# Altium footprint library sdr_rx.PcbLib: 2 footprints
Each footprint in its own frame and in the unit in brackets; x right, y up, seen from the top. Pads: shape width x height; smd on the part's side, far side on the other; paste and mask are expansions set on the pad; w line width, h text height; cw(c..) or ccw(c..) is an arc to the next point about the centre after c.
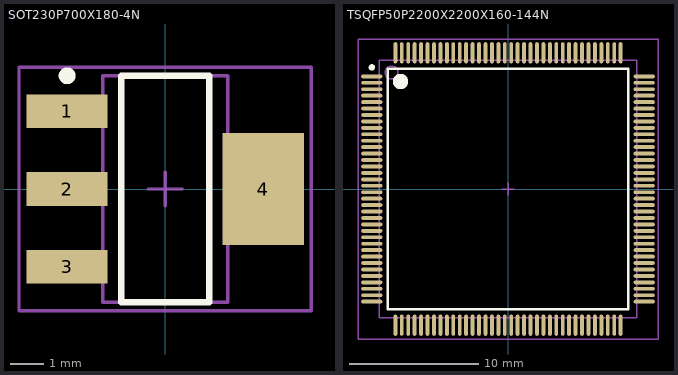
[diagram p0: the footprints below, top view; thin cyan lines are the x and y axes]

## SOT230P700X180-4N [mm] "SOT223, 4-Leads, Body 6.7x7.3mm (max), Pitch 2.30mm, IPC Medium Density"
height 1.8
pads (4):
  rect 2.4x1 smd: 1(-2.9,2.3) 2(-2.9,0) 3(-2.9,-2.3)
  rect 2.4x3.3 smd: 4(2.9,0)
Top Overlay:
  circle w0.25: c-2.9,3.35 r0.125
  lines w0.2: -1.3,-3.35 -1.3,3.35 1.3,3.35 1.3,-3.35 -1.3,-3.35
Mechanical 13:
  lines w0.1: -1.85,-3.35 -1.85,3.35 1.85,3.35 1.85,-3.35 -1.85,-3.35
Mechanical 15:
  lines w0.1: -0.5,0 0.5,0 ; 0,-0.5 0,0.5 ; -4.325,-3.6 -4.325,3.6 4.325,3.6 4.325,-3.6 -4.325,-3.6
3D body: height 1.8, standoff 0.02, extent -1.85,-3.35 1.85,3.35

## TSQFP50P2200X2200X160-144N [mm] "TSQFP, 144-Leads, Body 22.0x22.0mm (max), Pitch 0.50mm, IPC Medium Density"
height 1.6
pads (144):
  oval 1.65x0.3 smd: 1(-10.575,8.75) 2(-10.575,8.25) 3(-10.575,7.75) 4(-10.575,7.25) 5(-10.575,6.75) 6(-10.575,6.25) 7(-10.575,5.75) 8(-10.575,5.25) 9(-10.575,4.75) 10(-10.575,4.25) 11(-10.575,3.75) 12(-10.575,3.25) 13(-10.575,2.75) 14(-10.575,2.25) 15(-10.575,1.75) 16(-10.575,1.25) 17(-10.575,0.75) 18(-10.575,0.25) 19(-10.575,-0.25) 20(-10.575,-0.75) 21(-10.575,-1.25) 22(-10.575,-1.75) 23(-10.575,-2.25) 24(-10.575,-2.75) 25(-10.575,-3.25) 26(-10.575,-3.75) 27(-10.575,-4.25) 28(-10.575,-4.75) 29(-10.575,-5.25) 30(-10.575,-5.75) 31(-10.575,-6.25) 32(-10.575,-6.75) 33(-10.575,-7.25) 34(-10.575,-7.75) 35(-10.575,-8.25) 36(-10.575,-8.75) 73(10.575,-8.75) 74(10.575,-8.25) 75(10.575,-7.75) 76(10.575,-7.25) 77(10.575,-6.75) 78(10.575,-6.25) 79(10.575,-5.75) 80(10.575,-5.25) 81(10.575,-4.75) 82(10.575,-4.25) 83(10.575,-3.75) 84(10.575,-3.25) 85(10.575,-2.75) 86(10.575,-2.25) 87(10.575,-1.75) 88(10.575,-1.25) 89(10.575,-0.75) 90(10.575,-0.25) 91(10.575,0.25) 92(10.575,0.75) 93(10.575,1.25) 94(10.575,1.75) 95(10.575,2.25) 96(10.575,2.75) 97(10.575,3.25) 98(10.575,3.75) 99(10.575,4.25) 100(10.575,4.75) 101(10.575,5.25) 102(10.575,5.75) 103(10.575,6.25) 104(10.575,6.75) 105(10.575,7.25) 106(10.575,7.75) 107(10.575,8.25) 108(10.575,8.75)
  oval 0.3x1.65 smd: 37(-8.75,-10.575) 38(-8.25,-10.575) 39(-7.75,-10.575) 40(-7.25,-10.575) 41(-6.75,-10.575) 42(-6.25,-10.575) 43(-5.75,-10.575) 44(-5.25,-10.575) 45(-4.75,-10.575) 46(-4.25,-10.575) 47(-3.75,-10.575) 48(-3.25,-10.575) 49(-2.75,-10.575) 50(-2.25,-10.575) 51(-1.75,-10.575) 52(-1.25,-10.575) 53(-0.75,-10.575) 54(-0.25,-10.575) 55(0.25,-10.575) 56(0.75,-10.575) 57(1.25,-10.575) 58(1.75,-10.575) 59(2.25,-10.575) 60(2.75,-10.575) 61(3.25,-10.575) 62(3.75,-10.575) 63(4.25,-10.575) 64(4.75,-10.575) 65(5.25,-10.575) 66(5.75,-10.575) 67(6.25,-10.575) 68(6.75,-10.575) 69(7.25,-10.575) 70(7.75,-10.575) 71(8.25,-10.575) 72(8.75,-10.575) 109(8.75,10.575) 110(8.25,10.575) 111(7.75,10.575) 112(7.25,10.575) 113(6.75,10.575) 114(6.25,10.575) 115(5.75,10.575) 116(5.25,10.575) 117(4.75,10.575) 118(4.25,10.575) 119(3.75,10.575) 120(3.25,10.575) 121(2.75,10.575) 122(2.25,10.575) 123(1.75,10.575) 124(1.25,10.575) 125(0.75,10.575) 126(0.25,10.575) 127(-0.25,10.575) 128(-0.75,10.575) 129(-1.25,10.575) 130(-1.75,10.575) 131(-2.25,10.575) 132(-2.75,10.575) 133(-3.25,10.575) 134(-3.75,10.575) 135(-4.25,10.575) 136(-4.75,10.575) 137(-5.25,10.575) 138(-5.75,10.575) 139(-6.25,10.575) 140(-6.75,10.575) 141(-7.25,10.575) 142(-7.75,10.575) 143(-8.25,10.575) 144(-8.75,10.575)
Top Overlay:
  circle w0.25: c-10.575,9.45 r0.125
  circle w0.6: c-8.35,8.35 r0.3
  lines w0.2: -9.35,-9.35 -9.35,9.35 9.35,9.35 9.35,-9.35 -9.35,-9.35
Mechanical 13:
  circle w0.1: c-9.05,9.05 r0.5
  lines w0.1: -10,-10 -10,10 10,10 10,-10 -10,-10
Mechanical 15:
  lines w0.1: -0.5,0 0.5,0 ; 0,-0.5 0,0.5 ; -11.65,-11.65 -11.65,11.65 11.65,11.65 11.65,-11.65 -11.65,-11.65
3D body: height 1.6, standoff 0.05, extent -10,-10 10,10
